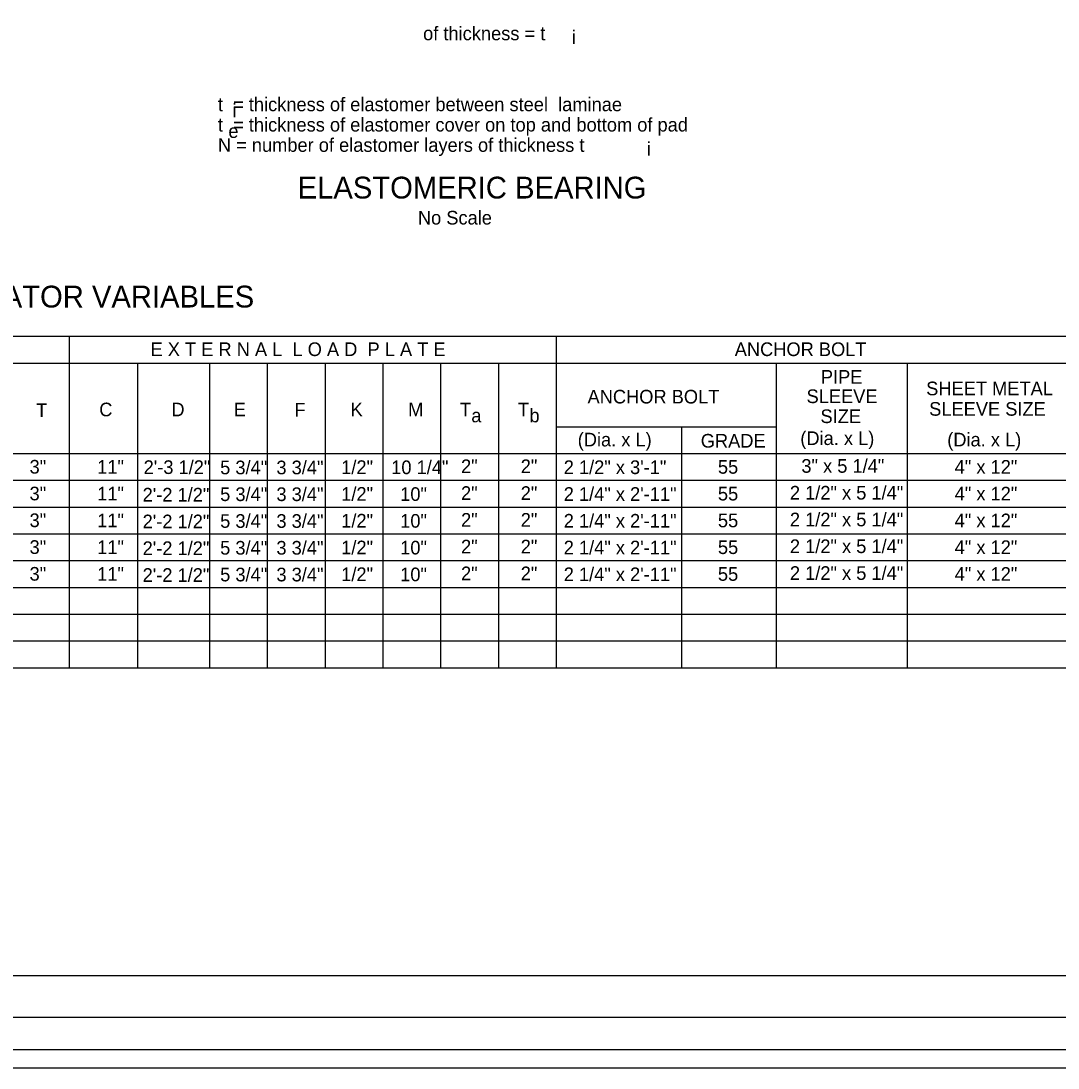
# Model space of a CAD drawing. Extents: x -194 to 226, y 505 to 725.
# Drawn here: x -47.4 to 47.6, y 505.4 to 601.4 of the extents above; entities that cross this region are included whole.
import ezdxf

# ---------------------------------------------------------------- set-up
doc = ezdxf.new("R2010")
doc.units = 0
for name, color, linetype in [('border', 7, 'Continuous'), ('Border 2660-Hwy18 - Level 62', 7, 'Continuous'), ('Border 2660-Hwy18 - Level 63', 7, 'Continuous'), ('Level 40', 7, 'Continuous'), ('Level 41', 7, 'Continuous'), ('Level 62 PDF', 7, 'Continuous')]:
    doc.layers.add(name, color=color, linetype=linetype)

msp = doc.modelspace()

# ---------------------------------------------------------------- linework, layer by layer
at = {"layer": 'border'}
msp.add_line((143.779, 513.86), (-176.332, 513.86), dxfattribs=at)
at = {"layer": 'Border 2660-Hwy18 - Level 62'}
msp.add_lwpolyline([(-192.533, 725.169), (148.651, 725.169), (148.651, 507.073), (-192.533, 507.073)], close=True, dxfattribs=at)
at = {"layer": 'Border 2660-Hwy18 - Level 63'}
msp.add_lwpolyline([(-193.644, 723.74), (146.351, 723.74), (146.351, 510.044), (-193.644, 510.044)], close=True, dxfattribs=at)
at = {"layer": 'Level 40'}
for p, q in [((-36.746, 570.011), (-36.746, 542.092)), ((-30.142, 570.011), (-30.142, 542.092)), ((-24.854, 570.011), (-24.854, 542.092)), ((-19.563, 570.011), (-19.563, 542.092)), ((-14.271, 570.011), (-14.271, 542.092)), ((-8.979, 570.011), (-8.979, 542.092)), ((-3.688, 570.011), (-3.688, 542.092)), ((0.214, 570.011), (5.33, 570.011)), ((21.757, 570.011), (21.757, 542.092)), ((33.757, 570.011), (33.757, 542.092)), ((1.604, 564.172), (21.757, 564.172)), ((13.084, 564.172), (13.084, 542.092)), ((-173.559, 561.719), (58.082, 561.719)), ((-42.997, 562.218), (-42.997, 558.728)), ((-36.746, 562.218), (-36.746, 558.728)), ((-30.142, 562.218), (-30.142, 558.728)), ((-24.854, 562.218), (-24.854, 558.728)), ((1.604, 562.218), (1.604, 558.728)), ((21.757, 562.218), (21.757, 558.728)), ((33.757, 562.218), (33.757, 558.728)), ((-173.559, 559.266), (58.082, 559.266)), ((-173.559, 556.812), (58.082, 556.812)), ((-173.559, 556.812), (58.082, 556.812)), ((-42.997, 557.311), (-42.997, 553.821)), ((-24.854, 557.311), (-24.854, 553.821)), ((21.757, 557.311), (21.757, 553.821)), ((-173.559, 554.359), (58.082, 554.359)), ((-173.559, 554.359), (58.082, 554.359)), ((-173.559, 551.906), (58.082, 551.906)), ((-173.559, 551.905), (58.082, 551.905)), ((-173.559, 549.452), (58.082, 549.452)), ((-173.559, 546.999), (58.082, 546.999)), ((-173.559, 544.545), (58.082, 544.545))]:
    msp.add_line(p, q, dxfattribs=at)
at = {"layer": 'Level 41'}
for p, q in [((-92.484, 572.464), (58.082, 572.464)), ((-42.997, 572.464), (-42.997, 542.092)), ((1.604, 572.464), (1.604, 542.092)), ((-173.559, 570.011), (58.082, 570.011)), ((-173.559, 542.092), (58.082, 542.092))]:
    msp.add_line(p, q, dxfattribs=at)
at = {"layer": 'Level 62 PDF'}
msp.add_lwpolyline([(-190.033, 723.503), (151.151, 723.503), (151.151, 505.407), (-190.033, 505.407)], close=True, dxfattribs=at)

# ---------------------------------------------------------------- texts
at = {"layer": 'Level 40'}
for s, p in [('of thickness = t', (-10.582, 599.588)), ('t  = thickness of elastomer between steel  laminae', (-29.384, 593.086)), ('t  = thickness of elastomer cover on top and bottom of pad', (-29.384, 591.224)), ('e', (-28.422, 590.636)), ('N = number of elastomer layers of thickness t', (-29.384, 589.363)), ('No Scale', (-11.059, 582.702)), ('E X T E R N A L  L O A D  P L A T E ', (-35.554, 570.65)), ('ANCHOR BOLT', (17.968, 570.65)), ('PIPE', (25.857, 568.117)), ('SHEET METAL', (35.506, 567.055)), ('ANCHOR BOLT', (4.482, 566.303)), ('SLEEVE', (24.546, 566.339)), ('T', (-46.037, 565.067)), ('C', (-40.252, 565.128)), ('D', (-33.644, 565.128)), ('E', (-27.931, 565.128)), ('F', (-22.376, 565.102)), ('K', (-17.224, 565.128)), ('M', (-11.952, 565.128)), ('T ', (-7.213, 565.128)), ('T ', (-1.884, 565.128)), ('SLEEVE SIZE', (35.779, 565.182)), ('a ', (-6.168, 564.577)), ('b ', (-0.839, 564.577)), ('SIZE', (25.822, 564.509)), ('(Dia. x L)', (3.581, 562.37)), ('GRADE', (14.854, 562.26)), ('(Dia. x L)', (23.974, 562.497)), ('(Dia. x L)', (37.435, 562.37)), ('3"', (-46.636, 559.882)), ('11"', (-40.439, 559.869)), ('2\'-3 1/2"', (-36.187, 559.843)), ('5 3/4"', (-29.174, 559.816)), ('3 3/4"', (-24.02, 559.816)), ('1/2"', (-18.083, 559.843)), ('10 1/4"', (-13.503, 559.83)), ('2"', (-7.107, 559.921)), ('2"', (-1.637, 559.921)), ('2 1/2" x 3\'-1"', (2.301, 559.836)), ('55', (16.425, 559.869)), ('3" x 5 1/4"', (24.071, 559.954)), ('4" x 12"', (38.116, 559.869)), ('3"', (-46.636, 557.429)), ('11"', (-40.439, 557.416)), ('2\'-2 1/2"', (-36.279, 557.321)), ('5 3/4"', (-29.174, 557.363)), ('3 3/4"', (-24.02, 557.363)), ('1/2"', (-18.083, 557.389)), ('10"', (-12.681, 557.376)), ('2"', (-7.107, 557.468)), ('2"', (-1.637, 557.468)), ('2 1/4" x 2\'-11"', (2.301, 557.383)), ('55', (16.425, 557.416)), ('2 1/2" x 5 1/4"', (23.02, 557.501)), ('4" x 12"', (38.116, 557.416)), ('3"', (-46.636, 554.976)), ('11"', (-40.439, 554.962)), ('2\'-2 1/2"', (-36.279, 554.867)), ('5 3/4"', (-29.174, 554.91)), ('3 3/4"', (-24.02, 554.909)), ('1/2"', (-18.083, 554.936)), ('10"', (-12.681, 554.923)), ('2"', (-7.107, 555.015)), ('2"', (-1.637, 555.015)), ('2 1/4" x 2\'-11"', (2.301, 554.93)), ('55', (16.425, 554.962)), ('2 1/2" x 5 1/4"', (23.02, 555.047)), ('4" x 12"', (38.116, 554.962)), ('3"', (-46.636, 552.522)), ('11"', (-40.439, 552.509)), ('2\'-2 1/2"', (-36.279, 552.414)), ('5 3/4"', (-29.174, 552.456)), ('3 3/4"', (-24.02, 552.456)), ('1/2"', (-18.083, 552.483)), ('10"', (-12.681, 552.47)), ('2"', (-7.107, 552.561)), ('2"', (-1.637, 552.561)), ('2 1/4" x 2\'-11"', (2.301, 552.476)), ('55', (16.425, 552.509)), ('2 1/2" x 5 1/4"', (23.02, 552.594)), ('4" x 12"', (38.116, 552.509)), ('3"', (-46.636, 550.069)), ('11"', (-40.439, 550.055)), ('2\'-2 1/2"', (-36.279, 549.96)), ('5 3/4"', (-29.174, 550.003)), ('3 3/4"', (-24.02, 550.003)), ('1/2"', (-18.083, 550.029)), ('10"', (-12.681, 550.016)), ('2"', (-7.107, 550.108)), ('2"', (-1.637, 550.108)), ('2 1/4" x 2\'-11"', (2.301, 550.023)), ('55', (16.425, 550.055)), ('2 1/2" x 5 1/4"', (23.02, 550.14)), ('4" x 12"', (38.116, 550.055))]:
    msp.add_text(s, height=1.25, dxfattribs=at).set_placement(p)
for p in [(3.037, 599.253), (-28.047, 592.531), (9.903, 589.014)]:
    msp.add_text('i', height=1.25, rotation=360, dxfattribs=at).set_placement(p)
at = {"layer": 'Level 41'}
for s, p in [(' ELASTOMERIC BEARING ', (-22.818, 585.085)), (' TABLE OF FABRICATOR VARIABLES ', (-73.315, 575.097))]:
    msp.add_text(s, height=2, dxfattribs=at).set_placement(p)

doc.saveas('drawing.dxf')
